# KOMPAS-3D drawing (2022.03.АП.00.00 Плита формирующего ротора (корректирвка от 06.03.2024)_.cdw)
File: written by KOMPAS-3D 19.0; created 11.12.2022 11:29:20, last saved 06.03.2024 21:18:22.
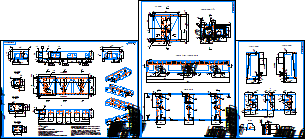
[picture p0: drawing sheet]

Sheet 1: A1, landscape
Sheet 2: A1, portrait
Sheet 3: A2, portrait

Document properties: Полное имя файла: G:\Кемерово чертежи\3. Плита формующего ротора\2022.03.АП.00.00 Плита формирующего ротора (корректирвка от 06.03.2024)_.cdw; Знак неуказанной шероховатости: 4; Параметр неуказанной шероховатости: Rz 160; Форматы листов документа: A2, 2xA1

Title block, sheet 1: Наименование: Плита формирующего / ротора; designation: 2022.03.АП.00.00; Материал: СЧ20  ГОСТ 1412-85; Масса: 153; scale: 1:4; sheet number: 1; Количество листов документа: 3; organisation: АгроПак; Форматы листов документа: A1; stored path: G:\Кемерово чертежи\3. Плита формующего ротора\Плита формирующего ротора_001.cdw; Разработал: Полынский МИ; Утвердил: Гордиенко ДС
Title block, sheet 2: sheet number: 2
Title block, sheet 3: sheet number: 3; Форматы листов документа: A2

Views: Вид 7, Вид 10, Вид 14, Выносной элемент 15, Вид 20, Вид 22, Вид 23, Выносной элемент А1, Выносной элемент
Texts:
  Rz 160
  Rz 160 ( )
Dimensions and other numbers on the sheet: 198; 10; 5; 20; 80; 325; 205; 156; 183; 2,5; 400; 41; 68; 120; 188; 128; 40; 130; 250; 460; 110; 1260; 16; 140; 560; 144; 200; 157,5; 50; 31; 22; 19; 210; 0,03; 395; 11; 378; 18; 72; 72   17 =; 1224; 30; 360; 60; 22,5; 355; 42,5; 70; 100; 170; 85; 156*; 358; 258; 90; 110*; 85   6 =; 255; 4 отв.; 12; 21; 25; 35; 8; 36 отв.; 1,25; 36 фасок; 65; 29; 15; 51; 97; 84; 77; 67; 126,5; 92,5; 38,,,40; 43; 7; 1:4; 153; 1; 3; 2022.03.АП.00.00; 2

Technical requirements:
  * - размер для справок.
  Изометрия приведена для наглядности.
  Равномерный уклон поверхности к краю отверстия  40 мм.
  Точность отливки 12-11-10-12 ГОСТ 26645-85.
  Линейные уклоны по ГОСТ 3212-92.
  Неуказанные литейные радиусы 3,,,10 мм.
  Все поверхности отливки перед механической обработкой должны
  быть очищены от  формовочной смеси, окалины и пригара, прибыли и
  питатели должны быть удалены.
  На подлежащей механической обработке поверхности не
  допускаются дефекты в виде трещин, раковин, спаев и т.д
  превышающие по глубине припуск на механическую обработку.
  Покрытие кроме обрабатываемых поверхностей Ж, И, выборки и
  отверстия на поверхности Ж, и резьбовых отверстий грунтовкой
  ГФ-021 ГОСТ 25125-82, эмалью в два слоя ПФ-115 желтая ГОСТ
